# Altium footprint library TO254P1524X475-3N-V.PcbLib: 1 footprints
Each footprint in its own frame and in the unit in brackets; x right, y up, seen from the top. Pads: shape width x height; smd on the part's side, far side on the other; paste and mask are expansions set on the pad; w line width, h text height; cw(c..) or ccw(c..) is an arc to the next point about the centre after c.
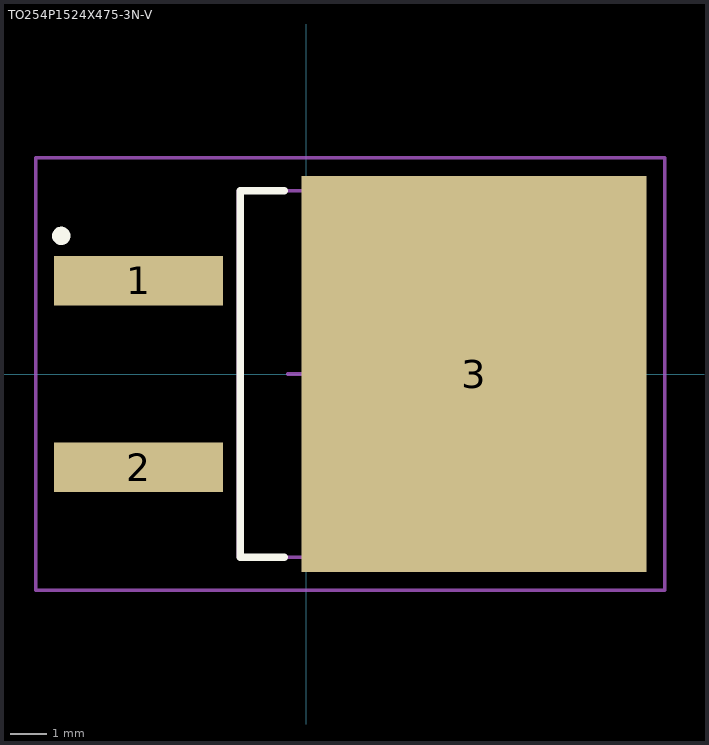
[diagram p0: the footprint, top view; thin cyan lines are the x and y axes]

## TO254P1524X475-3N-V [mm] "TO,2.54mm pitch;2 pin,15.245mm L X 9.25mm W X 4.75mm H body"
height 4.75
pads (3):
  rect 4.6x1.35 smd paste+0 mask+0: 1(-4.575,2.54) 2(-4.575,-2.54)
  rect 9.4x10.8 smd paste+0 mask+0: 3(4.575,0)
Top Overlay:
  circle w0.25: c-6.682,3.765 r0.125
  lines w0.2: -0.6,-5 -1.8,-5 -1.8,5 -0.6,5
M3 (ASY_Text_Top):
  text ".DESIGNATOR" at 0,0 h1.2
M13 (CMP_Body_OTL_Top):
  lines w0.1: -1.85,-5 7.4,-5 7.4,5 -1.85,5 -1.85,-5
  text "A" at -0.97,-2.95 h0.6
  text "K" at 4.255,-0.3 h0.6
  text "K" at -1.095,2.225 h0.6
M15 (CMP_Courtyard_Top):
  lines w0.1: -0.5,0 0.5,0 ; 0,-0.5 0,0.5 ; -7.375,-5.9 9.775,-5.9 9.775,5.9 -7.375,5.9 -7.375,-5.9
3D body "PG-TO263-2-1.STEP": height 4.51, standoff 0, extent -6.468,-5 8.525,5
